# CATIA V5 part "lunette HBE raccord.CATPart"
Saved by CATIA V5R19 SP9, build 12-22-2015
Part number: Part1
Bounding box of the stored display mesh (mm): x -60 to 0, y -20 to 100, z 0 to 24.491
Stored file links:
  C:\Users\hbezard\Documents\Perso\imprimante 3d\pieces\lunette transport\lunette HBE raccord.CATPart
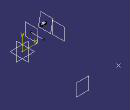
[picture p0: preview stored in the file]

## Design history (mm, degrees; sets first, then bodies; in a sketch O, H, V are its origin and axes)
Set1
  Plane1: type Offset, RefPlane zx-plane, Offset 100
  Plane2: type Offset, RefPlane yz-plane, Offset 60, reversed
  Point1: (-60, 100, 0)
  Line1: type PtDir, RefPoint {point type Coord, X -35, Y 0, Z 0}, Direction (0, 1, 0), Start 0, End 20
  Plane3: type Normal, Curve Sketch8, RefPoint Sketch8.P6
  Plane4: type OffsetPt, RefPlane yz-plane, RefPoint vertex of Line1
Body1 (main body)
  Sketch1 on zx-plane, origin (0, 0, 0), H (0, 0, 1), V (1, 0, 0)
    point P1 (-13, 0)
    line L1 (-13, 0) -> (-13, -9)
    line L2 (-13, -9) -> (1.4, -4.8)
    arc A1 centre (0, 0) radius 5 from (1.4, -4.8) to (5, 0) ccw
    point P4 (0, 0)
    point P5 (5, 0)
    line L3 (5, 0) -> (-13, 0)
    reference intersected line E1 through (0, 0) direction (0, 1) from xy-plane
    length L2 = 15
    length L1 = 9
    radius A1 = 5
    coincidence: P1 H, P5 H, P4 L3, P4 E1
    vertical: L1 V
    tangency: A1 L2
    horizontal: L3 H
  Pad1: profile Sketch1, direction (0, 1, 0), length 5, mirrored extent
  Sketch2 on Plane2, origin (-60, 0, 0), H (0, 1, 0), V (0, 0, 1)
    circle A1 centre (100, 0) radius 10
    reference projected point E1 (100, 0) from Point1
    radius A1 = 10
    concentricity: A1 E1
  Pad2: profile Sketch2, direction (1, 0, 0), length 5, mirrored extent
  Sketch3 on xy-plane, origin (0, 0, 0), H (1, 0, 0), V (0, 1, 0)
    arc A1 centre (-9.5, 0) radius 3 from (-6.5, 0) to (-11, 2.5981) ccw
    point P1 (-9.5, 0)
    arc A2 centre (-12.5, 0) radius 3 from (-9.5, 0) to (-11, 2.5981) ccw
    point P2 (-12.5, 0)
    reference intersected line E1 through (0, 0) direction (-1, 0) from zx-plane
    reference intersected line E2 through (0, 0) direction (-1, 0) from zx-plane
    axis line L1 (-35, 5.0345) -> (-35, -8.3344)
    arc A3 centre (-9.5, 0) radius 3 from (-11, -2.5981) to (-6.5, 0) ccw
    point P5 (-6.5, 0)
    point P6 (-6.5, 0)
    arc A4 centre (-12.5, 0) radius 3 from (-11, -2.5981) to (-9.5, 0) ccw
    point P7 (-9.5, 0)
    point P8 (-9.5, 0)
    reference projected line E3 (-35, -20) -> (-35, 0) from Line1
    distance P2 P1 = 3
    radius A2 = 3
    radius A1 = 3
    distance L1 P2 = 22.5
    coincidence: P2 E1, P1 E2, A1 A3, A2 A4, L1 E3, P5 P6, P7 P8
    vertical: L1 V
Body2
  Sketch4 on xy-plane, origin (0, 0, 0), H (1, 0, 0), V (0, 1, 0)
    arc A1 centre (-9.5, 0) radius 3 from (-6.5, 0) to (-11, 2.5981) ccw
    point P1 (-9.5, 0)
    arc A2 centre (-12.5, 0) radius 3 from (-9.5, 0) to (-11, 2.5981) ccw
    point P2 (-12.5, 0)
    reference intersected line E1 through (0, 0) direction (-1, 0) from zx-plane
    reference intersected line E2 through (0, 0) direction (-1, 0) from zx-plane
    axis line L1 (-35, 5.0345) -> (-35, -8.3344)
    arc A3 centre (-9.5, 0) radius 3 from (-11, -2.5981) to (-6.5, 0) ccw
    point P5 (-6.5, 0)
    point P6 (-6.5, 0)
    arc A4 centre (-12.5, 0) radius 3 from (-11, -2.5981) to (-9.5, 0) ccw
    point P7 (-9.5, 0)
    point P8 (-9.5, 0)
    reference projected line E3 (-35, -20) -> (-35, 0) from Line1
    distance P2 P1 = 3
    radius A2 = 3
    radius A1 = 3
    distance L1 P2 = 22.5
    coincidence: P2 E1, P1 E2, A1 A3, A2 A4, L1 E3, P5 P6, P7 P8
    vertical: L1 V
  Shaft1: profile Sketch4, axis Sketch4.L1, angle 360
  Sketch5 on xy-plane, origin (0, 0, 0), H (1, 0, 0), V (0, 1, 0)
    arc A1 centre (-65, 3) radius 3 from (-62.0114, 2.7389) to (-62.4019, 4.5) ccw
    point P1 (-65, 3)
    point P2 (-65, 6)
    construction line L1 (-65, 28.8094) -> (-65, 9.3354)
    arc A2 centre (-65, 3) radius 3 from (-67.5981, 4.5) to (-62.0114, 2.7389) ccw
    point P5 (-62.0114, 2.7389)
    point P6 (-62.0114, 2.7389)
    arc A3 centre (-65, 6) radius 3 from (-67.5981, 4.5) to (-62.4019, 4.5) ccw
    axis line L2 (-77.6916, 28.5) -> (-47.473, 28.5)
    reference intersected line E1 through (0, 0) direction (-1, 0) from zx-plane
    reference intersected line E2 through (-60, 0) direction (0, 1) from Plane2
    distance P2 P1 = 3
    radius A1 = 3
    distance A2 E1 = 0
    radius A3 = 3
    distance P2 L2 = 22.5
    distance E2 L1 = 5
    perpendicularity: L2 L1
    coincidence: P6 P5, P2 L1, P1 L1
  Shaft2: profile Sketch5, axis Sketch5.L2, angle 360
  Sketch6 on zx-plane, origin (0, 0, 0), H (0, 0, 1), V (1, 0, 0)
    spline S1 through (4.1715, -8.1459) (9.4122, -4.3898) (11.2076, 0)
    spline S2 through (-9.9293, -8.9423) (-1.2054, -5.9306) (5.1855, -2.8953) (6.3824, 0)
    projected circle E1 centre (0, -35) radius 28.5 from edge [face of Shaft1 from Sketch4.A1 | face of Shaft1 from Sketch4.A3]
    line L1 (6.3824, 0) -> (11.2076, 0)
    point P1 (6.3824, 0)
    point P2 (11.2076, 0)
    offset circle E3 centre (0, -35) radius 28 from edge [face of Shaft1 from Sketch4.A1 | face of Shaft1 from Sketch4.A3]
    offset arc E4 centre (0, -35) radius 28 from (5.5614, -7.5579) to (-9.3263, -8.5989) ccw from edge [face of Shaft1 from Sketch4.A1 | face of Shaft1 from Sketch4.A3]
    point P5 (11.2076, 0)
    point P6 (6.3824, 0)
    coincidence: P5 H, P6 H, P6 P1, P5 P2
    horizontal: L1 H
  Pad3: profile Sketch6, direction (0, 1, 0), length 2
  Fillet1: radius 9, on edge [start face of Pad3 | face of Shaft1 from Sketch4.A3]
  Fillet2: radius 0.11, on edge [face of Pad3 from Sketch6.E4 | end face of Pad3]
  Fillet3: radius 0.11, on edge [face of Pad3 from Sketch6.E4 | face of Shaft1 from Sketch4.A1]
  Fillet4: radius 1.11, on edge [face of Pad3 from Sketch6.S2 | end face of Pad3]
  Fillet5: radius 0.5, on edge [start face of Pad3 | face of Pad3 from Sketch6.S2]
  Fillet6: radius 0.5, on edge [face of Pad3 from Sketch6.S1 | end face of Pad3]; edge [start face of Pad3 | face of Pad3 from Sketch6.S1]
  Fillet7: radius 0.5, on edge [face of Pad3 from Sketch6.S1 | face of Shaft1]
  Fillet8: radius 1.5, on edge [face of Shaft1 | face of Shaft2 from Sketch5.A2]
  Sketch7 on Plane2, origin (-60, 0, 0), H (0, 1, 0), V (0, 0, 1)
    projected arc E1 centre (28.5, 0) radius 25.7611 from (4.3445, -8.9523) to (4.3445, 8.9523) ccw from edge [face of Shaft2 from Sketch5.A2 | face of Shaft2 from Sketch5.A1]
    projected arc E2 centre (28.5, 0) radius 25.7611 from (53.122, -7.5755) to (49.9464, 14.2718) ccw from edge [face of Shaft2 from Sketch5.A2 | face of Shaft2 from Sketch5.A1]
    spline S1 through (120.7164, 3.9449) (107.5754, 9.7962) (99.1692, 11.522) (81.7803, 8.4657) (71.4697, 3.3588) (57.2526, -5.1849) (50.7179, -8.9184)
    spline S2 through (122.3171, 6.7756) (113.4231, 11.1212) (98.9336, 15.2605) (56.852, 12.0692) (48.814, 14.811)
    arc A1 centre (121.5271, 5.3544) radius 1.626 from (120.7164, 3.9449) to (122.3171, 6.7756) ccw
    point P3 (120.7164, 3.9449)
    point P4 (122.3171, 6.7756)
    point P8 (120.7164, 3.9449)
    point P9 (122.3171, 6.7756)
    coincidence: P8 P3, P9 P4
    tangency: A1 S1, A1 S2
  Pad4: profile Sketch7, direction (-1, 0, 0), length 3
  Fillet9: radius 2, on edge [face of Pad4 from Sketch7.E2 | face of Shaft2 from Sketch5.A1]
  Fillet10: radius 1.5, on edge [face of Pad4 from Sketch7.E2 | start face of Pad4]
  Fillet11: radius 1.5, on edge [face of Pad4 from Sketch7.S2 | start face of Pad4]
  Fillet12: radius 1.5, on end face of Pad4
  Mirror1: of the body so far, about yz-plane
Body3
  Sketch8 on zx-plane, origin (0, 0, 0), H (-1, 0, 0), V (0, 0, 1)
    arc A1 centre (35, 0) radius 22.5 from (38.9071, 22.1582) to (31.0929, 22.1582) ccw
    point P1 (35, 0)
    reference projected point E1 (35, 0) from vertex of Line1
    reference projected circle E2 centre (35, 0) radius 25.5 from edge [face of Shaft1 from Sketch4.A4 | face of Shaft1 from Sketch4.A2]
    axis line L1 (35, 7.5958) -> (35, -7.5958)
    construction line L2 (35, 0) -> (31.0929, 22.1582)
    point P4 (35, 0)
    construction line L3 (35, 0) -> (38.9071, 22.1582)
    point P6 (38.9071, 22.1582)
    distance A1 E2 = 3
    angle L2 L1 = 10
    coincidence: P1 E1
    vertical: L1 V
    midpoint: L1 P1
    symmetry: P1 P4 L1, L2 L3 L1
  Sketch9 on Plane4, origin (-35, -20, 0), H (0, 1, 0), V (0, 0, 1)
    circle A1 centre (20, 22.5) radius 1
    point P1 (20, 22.5)
    circle A2 centre (20, 22.5) radius 2
    point P2 (20, 22.5)
    radius A1 = 1
    radius A2 = 2
    radius A2 = 2 (reference)
    coincidence: P1 P2
  Shaft3: profile Sketch9, axis Line1, angle 10, second angle 10
  Chamfer1: length 1, angle 30, on edge [face of Shaft3 | face of Shaft3 from Sketch9.A2]
  Chamfer2: length 1, angle 30, on edge [face of Shaft3 from Sketch9.A2 | face of Shaft3]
